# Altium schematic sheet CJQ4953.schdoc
size 127 x 101 mm
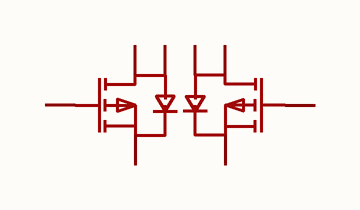
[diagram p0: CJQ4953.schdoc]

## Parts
Q?  cjq4953  [SOP-8_L4.9-W3.8-P1.27-LS6.0-BL]  (value not drawn)

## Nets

Not connected (* = marked no-connect by the designer): Q? 1(S) 2(G) 3(S) 4(G) 5(D) 6(D) 7(D) 8(D)

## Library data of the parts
Q? = cjq4953: 数量:2个P沟道;漏源电压(Vdss):30V;连续漏极电流(Id):5A;导通电阻(RDS(on)):60mΩ@10V;耗散功率(Pd):1.25W;阈值电压(Vgs(th)):1V;; Manufacturer: CJ(江苏长电/长晶); AddInBom: yes; ModelId: 0b80c7b2222d4c27a59de7b60fa3a3b4; ModelTransform: 192.913,236.22,0,0,0,0,0,0,0; Number: 2个P沟道; Drain to Source Voltage: 30V; Current - Continuous Drain(Id): 5A; Pd - Power Dissipation: 1.25W; Gate Threshold Voltage (Vgs(th)): 1V; Gate Charge(Qg): 25nC@10V; Type: P沟道; Vgs: ±20V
